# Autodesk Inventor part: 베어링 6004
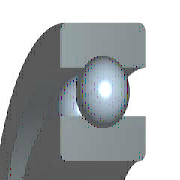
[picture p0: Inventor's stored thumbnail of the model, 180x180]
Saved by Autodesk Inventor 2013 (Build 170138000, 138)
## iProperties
IsCustomPart: 1
Created: 2012-02
Part Number: 베어링 6004
Material: 강철, 연강
Description: 깊은 그루브 볼 베어링
Document SubType Name: Modeling
Standard: KS B 2023
Designer: mduedu
Standards Organization: KS
Language: ko-KR
Size Designation: 6004 - 20 x 42 x 12
Categories: <MemberInstance><Categories><Category DisplayName="샤프트 부품" InternalName="7f7aeb1f-a693-4053-b835-cee3144e0d98" Mnemonic="SHFT"><Category DisplayName="베어링" Inter
Density: 1 g/cm^3
Author: mduedu
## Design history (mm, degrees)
sketch "스케치" dims "d0" = 5.72 (= -0.26 x WD + 0.26 x BD)
  geometry: L1 (3.14, 15.5)-(8.86, 15.5); L2 (6, 15.5)-(6, 12.64); L3 (6, 15.5)-(6, 18.36); L4 (3.875, 13.586)-(0, 13.586); L5 (0, 10)-(12, 10); L6 (3.875, 17.414)-(0, 17.414); L7 (0, 21)-(12, 21); L8 (12, 10)-(12, 13.586); L9 (8.125, 13.586)-(12, 13.586); L10 (8.125, 17.414)-(12, 17.414); L11 (12, 21)-(12, 17.414); L12 (-1.4, 0)-(8.4, 0) reference; L13 (0, -0.3)-(0, 5.3) reference
  constraints: 22 end point, 4 point on line, 2 collinear, 2 perpendicular, 2 symmetric about line, 1 midpoint, 1 parallel, 14 other
  dimensions: "d9" = 20 diameter of L5 L12 (= WD); "d11" = 42 diameter of L7 L12 (= BD); "d12" = 12 distance between parallel lines of L8 L13 (= KB); "d13" = 27.172 diameter of L9 L12 (= 0.326 x BD + 0.674 x WD)
revolve "본체" stored, may be unused: angle "d6" = 90 deg
revolve "볼" stored, may be unused: angle "d7" = 90 deg
pattern_circular "IDS_ARRAYBALL[SIMPL:T]" dims angle "d3" = 360 deg
body "Solid1"
fillet "모깎기1" dims "d1" = 0.6 (= KRS)
other parameters: "WD" = 20 [user parameter; used in 5 equation terms], "BD" = 42 [user parameter; used in 5 equation terms], "KB" = 12 [user parameter; used in 1 equation term], "KRS" = 0.6 [user parameter; used in 1 equation term], "d4" = 0, "d5" = 0, "d8" = 0, "d14" = 0, "d15" = 0, "BBA" = 0 [user parameter], "BC0" = 5000000 [user parameter], "BC" = 9360000 [user parameter], "BR" = 21 (= 0.5 x BD) [user parameter]
